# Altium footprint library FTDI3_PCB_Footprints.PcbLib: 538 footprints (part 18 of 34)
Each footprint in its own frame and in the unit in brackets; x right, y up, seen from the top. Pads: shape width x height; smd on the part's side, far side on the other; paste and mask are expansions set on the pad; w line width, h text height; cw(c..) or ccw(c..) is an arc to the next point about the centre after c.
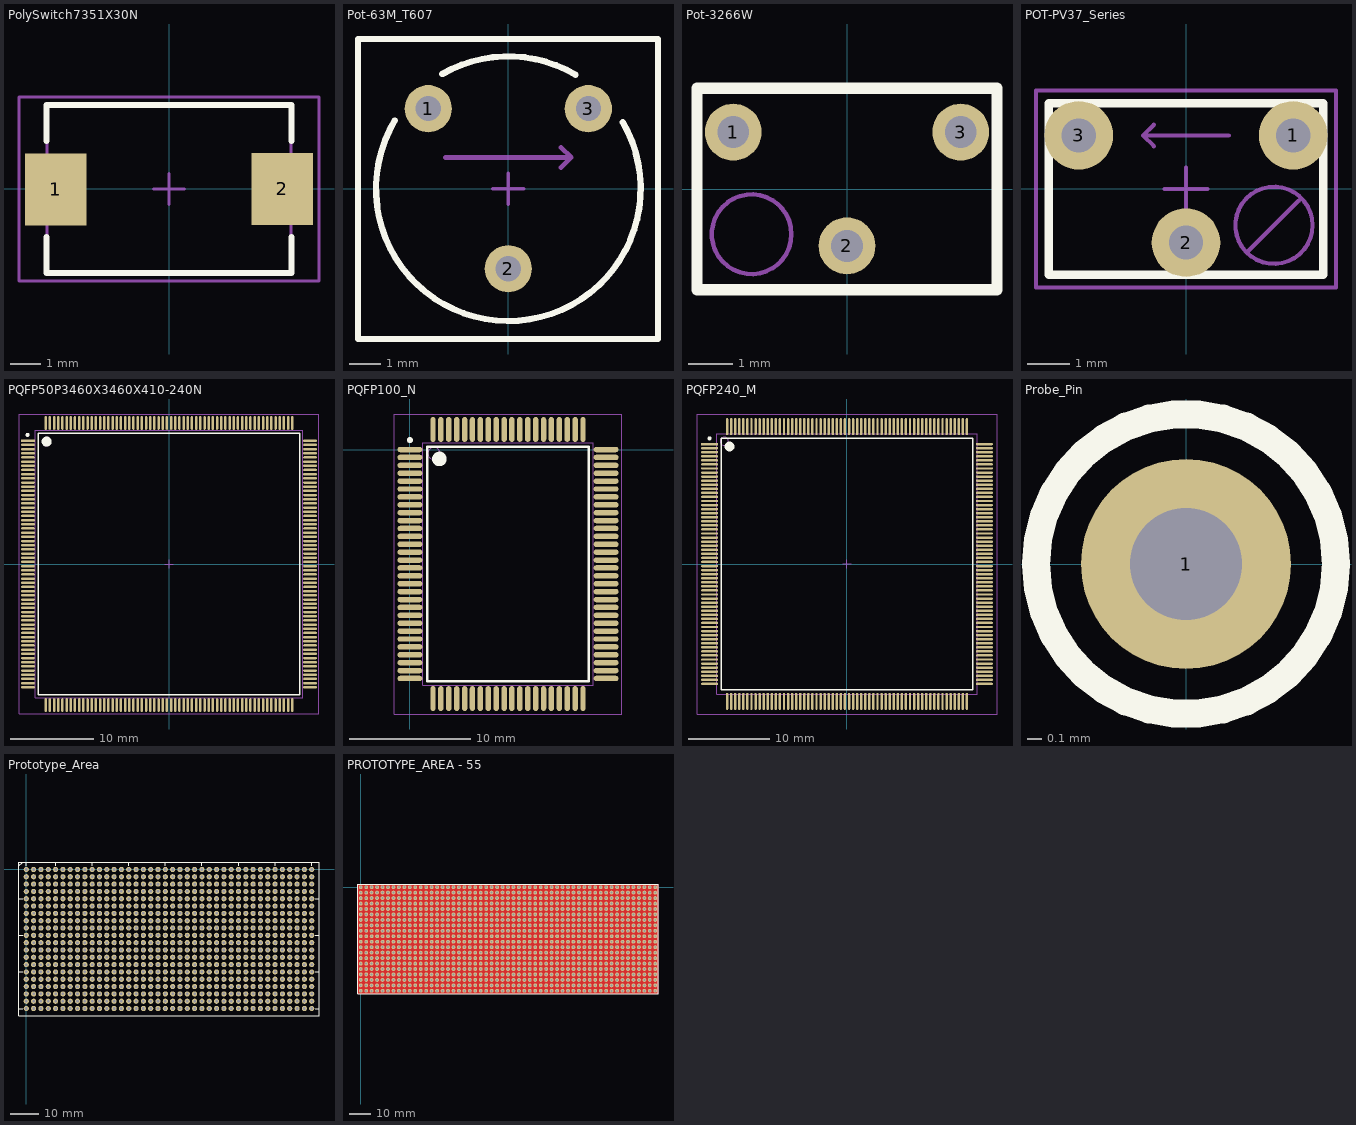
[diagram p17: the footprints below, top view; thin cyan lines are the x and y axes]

## PolySwitch7351X30N [mm] "PolySwitch; SMD300F, 2-Leads, Body 7.3x5.1mm, IPC Medium Density"
height 3
pads (2):
  rect 2x2.35 smd: 1(-3.7,-0.01) 2(3.7,0)
Top Overlay:
  lines w0.2: -4,-1.575 -4,-2.75 4,-2.75 4,-1.575 ; -4,1.575 -4,2.75 4,2.75 4,1.575
M13_Assembly_Info:
  lines w0.1: -3.99,-2.72 -3.99,2.72 3.99,2.72 3.99,-2.72 -3.99,-2.72
M15_Country_Yard:
  lines w0.1: -0.5,0 0.5,0 ; 0,-0.5 0,0.5 ; -4.9,-3 -4.9,3 4.9,3 4.9,-3 -4.9,-3
3D body: height 3, standoff 0, extent -3.99,-2.72 3.99,2.72

## Pot-63M_T607 [mm] "Finger adjustable cermet trimmer"
pads (3):
  round 1.5 hole 0.8: 1(-2.54,2.54) 2(0,-2.54) 3(2.54,2.54)
Top Overlay:
  lines w0.2: -3.601,2.161 ccw(c0,0) 3.634,2.105 ; -2.1,3.638 cw(c0,0) 2.131,3.619 ; -4.77,-4.77 -4.77,4.75 4.75,4.75 4.75,-4.77 -4.77,-4.77
M13_Assembly_Info:
  lines w0.15: -2,0.99 1.99,0.99 ; 1.67,0.67 1.99,0.99 ; 1.67,1.31 1.99,0.99
  text "CW" at -0.71,1.32 h0.8
M15_Country_Yard:
  lines w0.1: -0.5,0 0.5,0 ; 0,-0.5 0,0.5

## Pot-3266W [mil] "Potentiometer"
pads (3):
  round 50 hole 28: 1(-100,50) 2(0,-50) 3(100,50)
Top Overlay:
  lines w10: -131.89,-88.58 -131.89,88.58 131.89,88.58 131.89,-88.58 -131.89,-88.58
M13_Assembly_Info:
  circle w3.94: c-83.86,-39.76 r35.04
  lines w3.94: -131.89,-88.58 -131.89,88.58 131.89,88.58 131.89,-88.58 -131.89,-88.58
3D body: height 0, standoff 0, extent -131.89,-88.58 131.89,88.58

## POT-PV37_Series [mm] "Potentiometer; Multiturn-12; PV37 series; Murata"
pads (3):
  round 1.6 hole 0.8: 1(2.5,1.25) 2(0,-1.25) 3(-2.5,1.25)
Top Overlay:
  lines w0.2: -3.2,-2 -3.2,2 3.2,2 3.2,-2 -3.2,-2
M13_Assembly_Info:
  circle w0.1: c2.053,-0.847 r0.9
  lines w0.1: -0.75,1 -1,1.25 ; -0.75,1.5 -1,1.25 ; 1,1.25 -1,1.25 ; 1.453,-1.447 2.628,-0.272 ; -3.2,-2 -3.2,2 3.2,2 3.2,-2 -3.2,-2
M15_Country_Yard:
  lines w0.1: -0.5,0 0.5,0 ; 0,-0.5 0,0.5 ; -3.5,-2.3 -3.5,2.3 3.5,2.3 3.5,-2.3 -3.5,-2.3

## PQFP50P3460X3460X410-240N [mm] "PQFP, 240-Leads, Body 34.6x34.6mm (max), Pitch 0.50mm, IPC Medium Density"
height 4.1
pads (240):
  rect 1.65x0.3 smd: 1(-16.875,14.75)
  oval 1.65x0.3 smd: 2(-16.875,14.25) 3(-16.875,13.75) 4(-16.875,13.25) 5(-16.875,12.75) 6(-16.875,12.25) 7(-16.875,11.75) 8(-16.875,11.25) 9(-16.875,10.75) 10(-16.875,10.25) 11(-16.875,9.75) 12(-16.875,9.25) 13(-16.875,8.75) 14(-16.875,8.25) 15(-16.875,7.75) 16(-16.875,7.25) 17(-16.875,6.75) 18(-16.875,6.25) 19(-16.875,5.75) 20(-16.875,5.25) 21(-16.875,4.75) 22(-16.875,4.25) 23(-16.875,3.75) 24(-16.875,3.25) 25(-16.875,2.75) 26(-16.875,2.25) 27(-16.875,1.75) 28(-16.875,1.25) 29(-16.875,0.75) 30(-16.875,0.25) 31(-16.875,-0.25) 32(-16.875,-0.75) 33(-16.875,-1.25) 34(-16.875,-1.75) 35(-16.875,-2.25) 36(-16.875,-2.75) 37(-16.875,-3.25) 38(-16.875,-3.75) 39(-16.875,-4.25) 40(-16.875,-4.75) 41(-16.875,-5.25) 42(-16.875,-5.75) 43(-16.875,-6.25) 44(-16.875,-6.75) 45(-16.875,-7.25) 46(-16.875,-7.75) 47(-16.875,-8.25) 48(-16.875,-8.75) 49(-16.875,-9.25) 50(-16.875,-9.75) 51(-16.875,-10.25) 52(-16.875,-10.75) 53(-16.875,-11.25) 54(-16.875,-11.75) 55(-16.875,-12.25) 56(-16.875,-12.75) 57(-16.875,-13.25) 58(-16.875,-13.75) 59(-16.875,-14.25) 60(-16.875,-14.75) 121(16.875,-14.75) 122(16.875,-14.25) 123(16.875,-13.75) 124(16.875,-13.25) 125(16.875,-12.75) 126(16.875,-12.25) 127(16.875,-11.75) 128(16.875,-11.25) 129(16.875,-10.75) 130(16.875,-10.25) 131(16.875,-9.75) 132(16.875,-9.25) 133(16.875,-8.75) 134(16.875,-8.25) 135(16.875,-7.75) 136(16.875,-7.25) 137(16.875,-6.75) 138(16.875,-6.25) 139(16.875,-5.75) 140(16.875,-5.25) 141(16.875,-4.75) 142(16.875,-4.25) 143(16.875,-3.75) 144(16.875,-3.25) 145(16.875,-2.75) 146(16.875,-2.25) 147(16.875,-1.75) 148(16.875,-1.25) 149(16.875,-0.75) 150(16.875,-0.25) 151(16.875,0.25) 152(16.875,0.75) 153(16.875,1.25) 154(16.875,1.75) 155(16.875,2.25) 156(16.875,2.75) 157(16.875,3.25) 158(16.875,3.75) 159(16.875,4.25) 160(16.875,4.75) 161(16.875,5.25) 162(16.875,5.75) 163(16.875,6.25) 164(16.875,6.75) 165(16.875,7.25) 166(16.875,7.75) 167(16.875,8.25) 168(16.875,8.75) 169(16.875,9.25) 170(16.875,9.75) 171(16.875,10.25) 172(16.875,10.75) 173(16.875,11.25) 174(16.875,11.75) 175(16.875,12.25) 176(16.875,12.75) 177(16.875,13.25) 178(16.875,13.75) 179(16.875,14.25) 180(16.875,14.75)
  oval 0.3x1.65 smd: 61(-14.75,-16.875) 62(-14.25,-16.875) 63(-13.75,-16.875) 64(-13.25,-16.875) 65(-12.75,-16.875) 66(-12.25,-16.875) 67(-11.75,-16.875) 68(-11.25,-16.875) 69(-10.75,-16.875) 70(-10.25,-16.875) 71(-9.75,-16.875) 72(-9.25,-16.875) 73(-8.75,-16.875) 74(-8.25,-16.875) 75(-7.75,-16.875) 76(-7.25,-16.875) 77(-6.75,-16.875) 78(-6.25,-16.875) 79(-5.75,-16.875) 80(-5.25,-16.875) 81(-4.75,-16.875) 82(-4.25,-16.875) 83(-3.75,-16.875) 84(-3.25,-16.875) 85(-2.75,-16.875) 86(-2.25,-16.875) 87(-1.75,-16.875) 88(-1.25,-16.875) 89(-0.75,-16.875) 90(-0.25,-16.875) 91(0.25,-16.875) 92(0.75,-16.875) 93(1.25,-16.875) 94(1.75,-16.875) 95(2.25,-16.875) 96(2.75,-16.875) 97(3.25,-16.875) 98(3.75,-16.875) 99(4.25,-16.875) 100(4.75,-16.875) 101(5.25,-16.875) 102(5.75,-16.875) 103(6.25,-16.875) 104(6.75,-16.875) 105(7.25,-16.875) 106(7.75,-16.875) 107(8.25,-16.875) 108(8.75,-16.875) 109(9.25,-16.875) 110(9.75,-16.875) 111(10.25,-16.875) 112(10.75,-16.875) 113(11.25,-16.875) 114(11.75,-16.875) 115(12.25,-16.875) 116(12.75,-16.875) 117(13.25,-16.875) 118(13.75,-16.875) 119(14.25,-16.875) 120(14.75,-16.875) 181(14.75,16.875) 182(14.25,16.875) 183(13.75,16.875) 184(13.25,16.875) 185(12.75,16.875) 186(12.25,16.875) 187(11.75,16.875) 188(11.25,16.875) 189(10.75,16.875) 190(10.25,16.875) 191(9.75,16.875) 192(9.25,16.875) 193(8.75,16.875) 194(8.25,16.875) 195(7.75,16.875) 196(7.25,16.875) 197(6.75,16.875) 198(6.25,16.875) 199(5.75,16.875) 200(5.25,16.875) 201(4.75,16.875) 202(4.25,16.875) 203(3.75,16.875) 204(3.25,16.875) 205(2.75,16.875) 206(2.25,16.875) 207(1.75,16.875) 208(1.25,16.875) 209(0.75,16.875) 210(0.25,16.875) 211(-0.25,16.875) 212(-0.75,16.875) 213(-1.25,16.875) 214(-1.75,16.875) 215(-2.25,16.875) 216(-2.75,16.875) 217(-3.25,16.875) 218(-3.75,16.875) 219(-4.25,16.875) 220(-4.75,16.875) 221(-5.25,16.875) 222(-5.75,16.875) 223(-6.25,16.875) 224(-6.75,16.875) 225(-7.25,16.875) 226(-7.75,16.875) 227(-8.25,16.875) 228(-8.75,16.875) 229(-9.25,16.875) 230(-9.75,16.875) 231(-10.25,16.875) 232(-10.75,16.875) 233(-11.25,16.875) 234(-11.75,16.875) 235(-12.25,16.875) 236(-12.75,16.875) 237(-13.25,16.875) 238(-13.75,16.875) 239(-14.25,16.875) 240(-14.75,16.875)
Top Overlay:
  circle w0.6: c-14.65,14.65 r0.3
  circle w0.25: c-16.925,15.45 r0.125
  lines w0.2: -15.65,-15.65 15.65,-15.65 15.65,15.65 -15.65,15.65 -15.65,-15.65
M13_Assembly_Info:
  circle w0.1: c-14.65,14.65 r0.5
  lines w0.1: -16,-16 16,-16 16,16 -16,16 -16,-16
M15_Country_Yard:
  lines w0.1: -0.5,0 0.5,0 ; 0,-0.5 0,0.5 ; -17.95,-17.95 17.95,-17.95 17.95,17.95 -17.95,17.95 -17.95,-17.95
3D body: height 4.1, standoff 0.5, extent -16,-16 16,16

## PQFP100_N [mm] "QFP, 100-Leads, Body 20x14mm, Pitch 0.65mm, IPC Medium Density"
height 3.4
pads (100):
  oval 2.05x0.45 smd: 1(0,0) 2(0,-0.65) 3(0,-1.3) 4(0,-1.95) 5(0,-2.6) 6(0,-3.25) 7(0,-3.9) 8(0,-4.55) 9(0,-5.2) 10(0,-5.85) 11(0,-6.5) 12(0,-7.15) 13(0,-7.8) 14(0,-8.45) 15(0,-9.1) 16(0,-9.75) 17(0,-10.4) 18(0,-11.05) 19(0,-11.7) 20(0,-12.35) 21(0,-13) 22(0,-13.65) 23(0,-14.3) 24(0,-14.95) 25(0,-15.6) 26(0,-16.25) 27(0,-16.9) 28(0,-17.55) 29(0,-18.2) 30(0,-18.85) 51(16.15,-18.85) 52(16.15,-18.2) 53(16.15,-17.55) 54(16.15,-16.9) 55(16.15,-16.25) 56(16.15,-15.6) 57(16.15,-14.95) 58(16.15,-14.3) 59(16.15,-13.65) 60(16.15,-13) 61(16.15,-12.35) 62(16.15,-11.7) 63(16.15,-11.05) 64(16.15,-10.4) 65(16.15,-9.75) 66(16.15,-9.1) 67(16.15,-8.45) 68(16.15,-7.8) 69(16.15,-7.15) 70(16.15,-6.5) 71(16.15,-5.85) 72(16.15,-5.2) 73(16.15,-4.55) 74(16.15,-3.9) 75(16.15,-3.25) 76(16.15,-2.6) 77(16.15,-1.95) 78(16.15,-1.3) 79(16.15,-0.65) 80(16.15,0)
  oval 0.45x2.05 smd: 31(1.9,-20.5) 32(2.55,-20.5) 33(3.2,-20.5) 34(3.85,-20.5) 35(4.5,-20.5) 36(5.15,-20.5) 37(5.8,-20.5) 38(6.45,-20.5) 39(7.1,-20.5) 40(7.75,-20.5) 41(8.4,-20.5) 42(9.05,-20.5) 43(9.7,-20.5) 44(10.35,-20.5) 45(11,-20.5) 46(11.65,-20.5) 47(12.3,-20.5) 48(12.95,-20.5) 49(13.6,-20.5) 50(14.25,-20.5) 81(14.25,1.65) 82(13.6,1.65) 83(12.95,1.65) 84(12.3,1.65) 85(11.65,1.65) 86(11,1.65) 87(10.35,1.65) 88(9.7,1.65) 89(9.05,1.65) 90(8.4,1.65) 91(7.75,1.65) 92(7.1,1.65) 93(6.45,1.65) 94(5.8,1.65) 95(5.15,1.65) 96(4.5,1.65) 97(3.85,1.65) 98(3.2,1.65) 99(2.55,1.65) 100(1.9,1.65)
Top Overlay:
  circle w0.25: c0,0.775 r0.125
  circle w0.6: c2.425,-0.775 r0.3
  lines w0.2: 1.425,-19.075 1.425,0.225 14.725,0.225 14.725,-19.075 1.425,-19.075
M13_Assembly_Info:
  circle w0.1: c1.975,-0.325 r0.5
  lines w0.1: 1.075,-19.425 1.075,0.575 15.075,0.575 15.075,-19.425 1.075,-19.425
M15_Country_Yard:
  lines w0.1: -1.275,-21.775 -1.275,2.925 17.425,2.925 17.425,-21.775 -1.275,-21.775
3D body: height 3.4, standoff 0, extent 1.075,-19.425 15.075,0.575

## PQFP240_M [mm] "Shrink QFP, 240-Leads, Body 32x32mm, Pitch 0.5mm, IPC Low Density"
height 4.1
pads (240):
  rect 2.1x0.3 smd: 1(-16.9,14.75)
  oval 2.1x0.3 smd: 2(-16.9,14.25) 3(-16.9,13.75) 4(-16.9,13.25) 5(-16.9,12.75) 6(-16.9,12.25) 7(-16.9,11.75) 8(-16.9,11.25) 9(-16.9,10.75) 10(-16.9,10.25) 11(-16.9,9.75) 12(-16.9,9.25) 13(-16.9,8.75) 14(-16.9,8.25) 15(-16.9,7.75) 16(-16.9,7.25) 17(-16.9,6.75) 18(-16.9,6.25) 19(-16.9,5.75) 20(-16.9,5.25) 21(-16.9,4.75) 22(-16.9,4.25) 23(-16.9,3.75) 24(-16.9,3.25) 25(-16.9,2.75) 26(-16.9,2.25) 27(-16.9,1.75) 28(-16.9,1.25) 29(-16.9,0.75) 30(-16.9,0.25) 31(-16.9,-0.25) 32(-16.9,-0.75) 33(-16.9,-1.25) 34(-16.9,-1.75) 35(-16.9,-2.25) 36(-16.9,-2.75) 37(-16.9,-3.25) 38(-16.9,-3.75) 39(-16.9,-4.25) 40(-16.9,-4.75) 41(-16.9,-5.25) 42(-16.9,-5.75) 43(-16.9,-6.25) 44(-16.9,-6.75) 45(-16.9,-7.25) 46(-16.9,-7.75) 47(-16.9,-8.25) 48(-16.9,-8.75) 49(-16.9,-9.25) 50(-16.9,-9.75) 51(-16.9,-10.25) 52(-16.9,-10.75) 53(-16.9,-11.25) 54(-16.9,-11.75) 55(-16.9,-12.25) 56(-16.9,-12.75) 57(-16.9,-13.25) 58(-16.9,-13.75) 59(-16.9,-14.25) 60(-16.9,-14.75) 121(16.9,-14.75) 122(16.9,-14.25) 123(16.9,-13.75) 124(16.9,-13.25) 125(16.9,-12.75) 126(16.9,-12.25) 127(16.9,-11.75) 128(16.9,-11.25) 129(16.9,-10.75) 130(16.9,-10.25) 131(16.9,-9.75) 132(16.9,-9.25) 133(16.9,-8.75) 134(16.9,-8.25) 135(16.9,-7.75) 136(16.9,-7.25) 137(16.9,-6.75) 138(16.9,-6.25) 139(16.9,-5.75) 140(16.9,-5.25) 141(16.9,-4.75) 142(16.9,-4.25) 143(16.9,-3.75) 144(16.9,-3.25) 145(16.9,-2.75) 146(16.9,-2.25) 147(16.9,-1.75) 148(16.9,-1.25) 149(16.9,-0.75) 150(16.9,-0.25) 151(16.9,0.25) 152(16.9,0.75) 153(16.9,1.25) 154(16.9,1.75) 155(16.9,2.25) 156(16.9,2.75) 157(16.9,3.25) 158(16.9,3.75) 159(16.9,4.25) 160(16.9,4.75) 161(16.9,5.25) 162(16.9,5.75) 163(16.9,6.25) 164(16.9,6.75) 165(16.9,7.25) 166(16.9,7.75) 167(16.9,8.25) 168(16.9,8.75) 169(16.9,9.25) 170(16.9,9.75) 171(16.9,10.25) 172(16.9,10.75) 173(16.9,11.25) 174(16.9,11.75) 175(16.9,12.25) 176(16.9,12.75) 177(16.9,13.25) 178(16.9,13.75) 179(16.9,14.25) 180(16.9,14.75)
  oval 0.3x2.1 smd: 61(-14.75,-16.9) 62(-14.25,-16.9) 63(-13.75,-16.9) 64(-13.25,-16.9) 65(-12.75,-16.9) 66(-12.25,-16.9) 67(-11.75,-16.9) 68(-11.25,-16.9) 69(-10.75,-16.9) 70(-10.25,-16.9) 71(-9.75,-16.9) 72(-9.25,-16.9) 73(-8.75,-16.9) 74(-8.25,-16.9) 75(-7.75,-16.9) 76(-7.25,-16.9) 77(-6.75,-16.9) 78(-6.25,-16.9) 79(-5.75,-16.9) 80(-5.25,-16.9) 81(-4.75,-16.9) 82(-4.25,-16.9) 83(-3.75,-16.9) 84(-3.25,-16.9) 85(-2.75,-16.9) 86(-2.25,-16.9) 87(-1.75,-16.9) 88(-1.25,-16.9) 89(-0.75,-16.9) 90(-0.25,-16.9) 91(0.25,-16.9) 92(0.75,-16.9) 93(1.25,-16.9) 94(1.75,-16.9) 95(2.25,-16.9) 96(2.75,-16.9) 97(3.25,-16.9) 98(3.75,-16.9) 99(4.25,-16.9) 100(4.75,-16.9) 101(5.25,-16.9) 102(5.75,-16.9) 103(6.25,-16.9) 104(6.75,-16.9) 105(7.25,-16.9) 106(7.75,-16.9) 107(8.25,-16.9) 108(8.75,-16.9) 109(9.25,-16.9) 110(9.75,-16.9) 111(10.25,-16.9) 112(10.75,-16.9) 113(11.25,-16.9) 114(11.75,-16.9) 115(12.25,-16.9) 116(12.75,-16.9) 117(13.25,-16.9) 118(13.75,-16.9) 119(14.25,-16.9) 120(14.75,-16.9) 181(14.75,16.9) 182(14.25,16.9) 183(13.75,16.9) 184(13.25,16.9) 185(12.75,16.9) 186(12.25,16.9) 187(11.75,16.9) 188(11.25,16.9) 189(10.75,16.9) 190(10.25,16.9) 191(9.75,16.9) 192(9.25,16.9) 193(8.75,16.9) 194(8.25,16.9) 195(7.75,16.9) 196(7.25,16.9) 197(6.75,16.9) 198(6.25,16.9) 199(5.75,16.9) 200(5.25,16.9) 201(4.75,16.9) 202(4.25,16.9) 203(3.75,16.9) 204(3.25,16.9) 205(2.75,16.9) 206(2.25,16.9) 207(1.75,16.9) 208(1.25,16.9) 209(0.75,16.9) 210(0.25,16.9) 211(-0.25,16.9) 212(-0.75,16.9) 213(-1.25,16.9) 214(-1.75,16.9) 215(-2.25,16.9) 216(-2.75,16.9) 217(-3.25,16.9) 218(-3.75,16.9) 219(-4.25,16.9) 220(-4.75,16.9) 221(-5.25,16.9) 222(-5.75,16.9) 223(-6.25,16.9) 224(-6.75,16.9) 225(-7.25,16.9) 226(-7.75,16.9) 227(-8.25,16.9) 228(-8.75,16.9) 229(-9.25,16.9) 230(-9.75,16.9) 231(-10.25,16.9) 232(-10.75,16.9) 233(-11.25,16.9) 234(-11.75,16.9) 235(-12.25,16.9) 236(-12.75,16.9) 237(-13.25,16.9) 238(-13.75,16.9) 239(-14.25,16.9) 240(-14.75,16.9)
Top Overlay:
  circle w0.6: c-14.45,14.45 r0.3
  circle w0.25: c-16.9,15.45 r0.125
  lines w0.2: -15.45,-15.45 15.45,-15.45 15.45,15.45 -15.45,15.45 -15.45,-15.45
M13_Assembly_Info:
  circle w0.1: c-15.1,15.1 r0.5
  lines w0.1: -16,-16 16,-16 16,16 -16,16 -16,-16
M15_Country_Yard:
  lines w0.1: -0.5,0 0.5,0 ; 0,-0.5 0,0.5 ; -18.45,-18.45 18.45,-18.45 18.45,18.45 -18.45,18.45 -18.45,-18.45
3D body: height 4.1, standoff 0, extent -16,-16 16,16

## Probe_Pin [mm] "Probe Pin"
height 4.6
pads (1):
  round 1.5 hole 0.8: 1(0,0)
Top Overlay:
  circle w0.2: c0,0 r1.07
3D body: height 3, standoff 0, extent -1.245,-1.25 1.25,1.24

## Prototype_Area [mm] "Prototype area; 40 cols x 20 rows"
pads (800):
  round 1.8 hole 0.9: 1(0,0) 2(2.54,0) 3(5.08,0) 4(7.62,0) 5(10.16,0) 6(12.7,0) 7(15.24,0) 8(17.78,0) 9(20.32,0) 10(22.86,0) 11(25.4,0) 12(27.94,0) 13(30.48,0) 14(33.02,0) 15(35.56,0) 16(38.1,0) 17(40.64,0) 18(43.18,0) 19(45.72,0) 20(48.26,0) 21(50.8,0) 22(53.34,0) 23(55.88,0) 24(58.42,0) 25(60.96,0) 26(63.5,0) 27(66.04,0) 28(68.58,0) 29(71.12,0) 30(73.66,0) 31(76.2,0) 32(78.74,0) 33(81.28,0) 34(83.82,0) 35(86.36,0) 36(88.9,0) 37(91.44,0) 38(93.98,0) 39(96.52,0) 40(99.06,0) ""(0,-48.26) ""(0,-45.72) ""(0,-43.18) ""(0,-40.64) ""(0,-38.1) ""(0,-35.56) ""(0,-33.02) ""(0,-30.48) ""(0,-27.94) ""(0,-25.4) ""(0,-22.86) ""(0,-20.32) ""(0,-17.78) ""(0,-15.24) ""(0,-12.7) ""(0,-10.16) ""(0,-7.62) ""(0,-5.08) ""(0,-2.54) ""(2.54,-48.26) ""(2.54,-45.72) ""(2.54,-43.18) ""(2.54,-40.64) ""(2.54,-38.1) ""(2.54,-35.56) ""(2.54,-33.02) ""(2.54,-30.48) ""(2.54,-27.94) ""(2.54,-25.4) ""(2.54,-22.86) ""(2.54,-20.32) ""(2.54,-17.78) ""(2.54,-15.24) ""(2.54,-12.7) ""(2.54,-10.16) ""(2.54,-7.62) ""(2.54,-5.08) ""(2.54,-2.54) ""(5.08,-48.26) ""(5.08,-45.72) ""(5.08,-43.18) ""(5.08,-40.64) ""(5.08,-38.1) ""(5.08,-35.56) ""(5.08,-33.02) ""(5.08,-30.48) ""(5.08,-27.94) ""(5.08,-25.4) ""(5.08,-22.86) ""(5.08,-20.32) ""(5.08,-17.78) ""(5.08,-15.24) ""(5.08,-12.7) ""(5.08,-10.16) ""(5.08,-7.62) ""(5.08,-5.08) ""(5.08,-2.54) ""(7.62,-48.26) ""(7.62,-45.72) ""(7.62,-43.18) ""(7.62,-40.64) ""(7.62,-38.1) ""(7.62,-35.56) ""(7.62,-33.02) ""(7.62,-30.48) ""(7.62,-27.94) ""(7.62,-25.4) ""(7.62,-22.86) ""(7.62,-20.32) ""(7.62,-17.78) ""(7.62,-15.24) ""(7.62,-12.7) ""(7.62,-10.16) ""(7.62,-7.62) ""(7.62,-5.08) ""(7.62,-2.54) ""(10.16,-48.26) ""(10.16,-45.72) ""(10.16,-43.18) ""(10.16,-40.64) ""(10.16,-38.1) ""(10.16,-35.56) ""(10.16,-33.02) ""(10.16,-30.48) ""(10.16,-27.94) ""(10.16,-25.4) ""(10.16,-22.86) ""(10.16,-20.32) ""(10.16,-17.78) ""(10.16,-15.24) ""(10.16,-12.7) ""(10.16,-10.16) ""(10.16,-7.62) ""(10.16,-5.08) ""(10.16,-2.54) ""(12.7,-48.26) ""(12.7,-45.72) ""(12.7,-43.18) ""(12.7,-40.64) ""(12.7,-38.1) ""(12.7,-35.56) ""(12.7,-33.02) ""(12.7,-30.48) ""(12.7,-27.94) ""(12.7,-25.4) ""(12.7,-22.86) ""(12.7,-20.32) ""(12.7,-17.78) ""(12.7,-15.24) ""(12.7,-12.7) ""(12.7,-10.16) ""(12.7,-7.62) ""(12.7,-5.08) ""(12.7,-2.54) ""(15.24,-48.26) ""(15.24,-45.72) ""(15.24,-43.18) ""(15.24,-40.64) ""(15.24,-38.1) ""(15.24,-35.56) ""(15.24,-33.02) ""(15.24,-30.48) ""(15.24,-27.94) ""(15.24,-25.4) ""(15.24,-22.86) ""(15.24,-20.32) ""(15.24,-17.78) ""(15.24,-15.24) ""(15.24,-12.7) ""(15.24,-10.16) ""(15.24,-7.62) ""(15.24,-5.08) ""(15.24,-2.54) ""(17.78,-48.26) ""(17.78,-45.72) ""(17.78,-43.18) ""(17.78,-40.64) ""(17.78,-38.1) ""(17.78,-35.56) ""(17.78,-33.02) ""(17.78,-30.48) ""(17.78,-27.94) ""(17.78,-25.4) ""(17.78,-22.86) ""(17.78,-20.32) ""(17.78,-17.78) ""(17.78,-15.24) ""(17.78,-12.7) ""(17.78,-10.16) ""(17.78,-7.62) ""(17.78,-5.08) ""(17.78,-2.54) ""(20.32,-48.26) ""(20.32,-45.72) ""(20.32,-43.18) ""(20.32,-40.64) ""(20.32,-38.1) ""(20.32,-35.56) ""(20.32,-33.02) ""(20.32,-30.48) ""(20.32,-27.94) ""(20.32,-25.4) ""(20.32,-22.86) ""(20.32,-20.32) ""(20.32,-17.78) ""(20.32,-15.24) ""(20.32,-12.7) ""(20.32,-10.16) ""(20.32,-7.62) ""(20.32,-5.08) ""(20.32,-2.54) ""(22.86,-48.26) ""(22.86,-45.72) ""(22.86,-43.18) ""(22.86,-40.64) ""(22.86,-38.1) ""(22.86,-35.56) ""(22.86,-33.02) ""(22.86,-30.48) ""(22.86,-27.94) ""(22.86,-25.4) ""(22.86,-22.86) ""(22.86,-20.32) ""(22.86,-17.78) ""(22.86,-15.24) ""(22.86,-12.7) ""(22.86,-10.16) ""(22.86,-7.62) ""(22.86,-5.08) ""(22.86,-2.54) ""(25.4,-48.26) ""(25.4,-45.72) ""(25.4,-43.18) ""(25.4,-40.64) ""(25.4,-38.1) ""(25.4,-35.56) ""(25.4,-33.02) ""(25.4,-30.48) ""(25.4,-27.94) ""(25.4,-25.4) ""(25.4,-22.86) ""(25.4,-20.32) ""(25.4,-17.78) ""(25.4,-15.24) ""(25.4,-12.7) ""(25.4,-10.16) ""(25.4,-7.62) ""(25.4,-5.08) ""(25.4,-2.54) ""(27.94,-48.26) ""(27.94,-45.72) ""(27.94,-43.18) ""(27.94,-40.64) ""(27.94,-38.1) ""(27.94,-35.56) ""(27.94,-33.02) ""(27.94,-30.48) ""(27.94,-27.94) ""(27.94,-25.4) ""(27.94,-22.86) ""(27.94,-20.32) ""(27.94,-17.78) ""(27.94,-15.24) ""(27.94,-12.7) ""(27.94,-10.16) ""(27.94,-7.62) ""(27.94,-5.08) ""(27.94,-2.54) ""(30.48,-48.26) ""(30.48,-45.72) ""(30.48,-43.18) ""(30.48,-40.64) ""(30.48,-38.1) ""(30.48,-35.56) ""(30.48,-33.02) ""(30.48,-30.48) ""(30.48,-27.94) ""(30.48,-25.4) ""(30.48,-22.86) ""(30.48,-20.32) ""(30.48,-17.78) ""(30.48,-15.24) ""(30.48,-12.7) ""(30.48,-10.16) ""(30.48,-7.62) ""(30.48,-5.08) ""(30.48,-2.54) ""(33.02,-48.26) ""(33.02,-45.72) ""(33.02,-43.18) ""(33.02,-40.64) ""(33.02,-38.1) ""(33.02,-35.56) ""(33.02,-33.02) ""(33.02,-30.48) ""(33.02,-27.94) ""(33.02,-25.4) ""(33.02,-22.86) ""(33.02,-20.32) ""(33.02,-17.78) ""(33.02,-15.24) ""(33.02,-12.7) ""(33.02,-10.16) ""(33.02,-7.62) ""(33.02,-5.08) ""(33.02,-2.54) ""(35.56,-48.26) ""(35.56,-45.72) ""(35.56,-43.18) ""(35.56,-40.64) ""(35.56,-38.1) ""(35.56,-35.56) ""(35.56,-33.02) ""(35.56,-30.48) ""(35.56,-27.94) ""(35.56,-25.4) ""(35.56,-22.86) ""(35.56,-20.32) ""(35.56,-17.78) ""(35.56,-15.24) ""(35.56,-12.7) ""(35.56,-10.16) ""(35.56,-7.62) ""(35.56,-5.08) ""(35.56,-2.54) ""(38.1,-48.26) ""(38.1,-45.72) ""(38.1,-43.18) ""(38.1,-40.64) ""(38.1,-38.1) ""(38.1,-35.56) ""(38.1,-33.02) ""(38.1,-30.48) ""(38.1,-27.94) ""(38.1,-25.4) ""(38.1,-22.86) ""(38.1,-20.32) ""(38.1,-17.78) ""(38.1,-15.24) ""(38.1,-12.7) ""(38.1,-10.16) ""(38.1,-7.62) ""(38.1,-5.08) ""(38.1,-2.54) ""(40.64,-48.26) ""(40.64,-45.72) ""(40.64,-43.18) ""(40.64,-40.64) ""(40.64,-38.1) ""(40.64,-35.56) ""(40.64,-33.02) ""(40.64,-30.48) ""(40.64,-27.94) ""(40.64,-25.4) ""(40.64,-22.86) ""(40.64,-20.32) ""(40.64,-17.78) ""(40.64,-15.24) ""(40.64,-12.7) ""(40.64,-10.16) ""(40.64,-7.62) ""(40.64,-5.08) ""(40.64,-2.54) ""(43.18,-48.26) ""(43.18,-45.72) ""(43.18,-43.18) ""(43.18,-40.64) ""(43.18,-38.1) ""(43.18,-35.56) ""(43.18,-33.02) ""(43.18,-30.48) ""(43.18,-27.94) ""(43.18,-25.4) ""(43.18,-22.86) ""(43.18,-20.32) ""(43.18,-17.78) ""(43.18,-15.24) ""(43.18,-12.7) ""(43.18,-10.16) ""(43.18,-7.62) ""(43.18,-5.08) ""(43.18,-2.54) ""(45.72,-48.26) ""(45.72,-45.72) ""(45.72,-43.18) ""(45.72,-40.64) ""(45.72,-38.1) ""(45.72,-35.56) ""(45.72,-33.02) ""(45.72,-30.48) ""(45.72,-27.94) ""(45.72,-25.4) ""(45.72,-22.86) ""(45.72,-20.32) ""(45.72,-17.78) ""(45.72,-15.24) ""(45.72,-12.7) ""(45.72,-10.16) ""(45.72,-7.62) ""(45.72,-5.08) ""(45.72,-2.54) ""(48.26,-48.26) ""(48.26,-45.72) ""(48.26,-43.18) ""(48.26,-40.64) ""(48.26,-38.1) ""(48.26,-35.56) ""(48.26,-33.02) ""(48.26,-30.48) ""(48.26,-27.94) ""(48.26,-25.4) ""(48.26,-22.86) ""(48.26,-20.32) ""(48.26,-17.78) ""(48.26,-15.24) ""(48.26,-12.7) ""(48.26,-10.16) ""(48.26,-7.62) ""(48.26,-5.08) ""(48.26,-2.54) ""(50.8,-48.26) ""(50.8,-45.72) ""(50.8,-43.18) ""(50.8,-40.64) ""(50.8,-38.1) ""(50.8,-35.56) ""(50.8,-33.02) ""(50.8,-30.48) ""(50.8,-27.94) ""(50.8,-25.4) ""(50.8,-22.86) ""(50.8,-20.32) ""(50.8,-17.78) ""(50.8,-15.24) ""(50.8,-12.7) ""(50.8,-10.16) ""(50.8,-7.62) ""(50.8,-5.08) ""(50.8,-2.54) ""(53.34,-48.26) ""(53.34,-45.72) ""(53.34,-43.18) ""(53.34,-40.64) ""(53.34,-38.1) ""(53.34,-35.56) ""(53.34,-33.02) ""(53.34,-30.48) ""(53.34,-27.94) ""(53.34,-25.4) ""(53.34,-22.86) ""(53.34,-20.32) ""(53.34,-17.78) ""(53.34,-15.24) ""(53.34,-12.7) ""(53.34,-10.16) ""(53.34,-7.62) ""(53.34,-5.08) ""(53.34,-2.54) ""(55.88,-48.26) ""(55.88,-45.72) ""(55.88,-43.18) ""(55.88,-40.64) ""(55.88,-38.1) ""(55.88,-35.56) ""(55.88,-33.02) ""(55.88,-30.48) ""(55.88,-27.94) ""(55.88,-25.4) ""(55.88,-22.86) ""(55.88,-20.32) ""(55.88,-17.78) ""(55.88,-15.24) ""(55.88,-12.7) ""(55.88,-10.16) ""(55.88,-7.62) ""(55.88,-5.08) ""(55.88,-2.54) ""(58.42,-48.26) ""(58.42,-45.72) ""(58.42,-43.18) ""(58.42,-40.64) ""(58.42,-38.1) ""(58.42,-35.56) ""(58.42,-33.02) ""(58.42,-30.48) ""(58.42,-27.94) ""(58.42,-25.4) ""(58.42,-22.86) ""(58.42,-20.32) ""(58.42,-17.78) ""(58.42,-15.24) ""(58.42,-12.7) ""(58.42,-10.16) ""(58.42,-7.62) ""(58.42,-5.08) ""(58.42,-2.54) ""(60.96,-48.26) ""(60.96,-45.72) ""(60.96,-43.18) ""(60.96,-40.64) ""(60.96,-38.1) ""(60.96,-35.56) ""(60.96,-33.02) ""(60.96,-30.48) ""(60.96,-27.94) ""(60.96,-25.4) ""(60.96,-22.86) ""(60.96,-20.32) ""(60.96,-17.78) ""(60.96,-15.24) ""(60.96,-12.7) ""(60.96,-10.16) ""(60.96,-7.62) ""(60.96,-5.08) ""(60.96,-2.54) ""(63.5,-48.26) ""(63.5,-45.72) ""(63.5,-43.18) ""(63.5,-40.64) ""(63.5,-38.1) ""(63.5,-35.56) ""(63.5,-33.02) ""(63.5,-30.48) ""(63.5,-27.94) ""(63.5,-25.4) ""(63.5,-22.86) ""(63.5,-20.32) ""(63.5,-17.78) ""(63.5,-15.24) ""(63.5,-12.7) ""(63.5,-10.16) ""(63.5,-7.62) ""(63.5,-5.08) ""(63.5,-2.54) ""(66.04,-48.26) ""(66.04,-45.72) ""(66.04,-43.18) ""(66.04,-40.64) ""(66.04,-38.1) ""(66.04,-35.56) ""(66.04,-33.02) ""(66.04,-30.48) ""(66.04,-27.94) ""(66.04,-25.4) ""(66.04,-22.86) ""(66.04,-20.32) ""(66.04,-17.78) ""(66.04,-15.24) ""(66.04,-12.7) ""(66.04,-10.16) ""(66.04,-7.62) ""(66.04,-5.08) ""(66.04,-2.54) ""(68.58,-48.26) ""(68.58,-45.72) ""(68.58,-43.18) ""(68.58,-40.64) ""(68.58,-38.1) ""(68.58,-35.56) ""(68.58,-33.02) ""(68.58,-30.48) ""(68.58,-27.94) ""(68.58,-25.4) ""(68.58,-22.86) ""(68.58,-20.32) ""(68.58,-17.78) ""(68.58,-15.24) ""(68.58,-12.7) ""(68.58,-10.16) ""(68.58,-7.62) ""(68.58,-5.08) ""(68.58,-2.54) ""(71.12,-48.26) ""(71.12,-45.72) ""(71.12,-43.18) ""(71.12,-40.64) ""(71.12,-38.1) ""(71.12,-35.56) ""(71.12,-33.02) ""(71.12,-30.48) ""(71.12,-27.94) ""(71.12,-25.4) ""(71.12,-22.86) ""(71.12,-20.32) ""(71.12,-17.78) ""(71.12,-15.24) ""(71.12,-12.7) ""(71.12,-10.16) ""(71.12,-7.62) ""(71.12,-5.08) ""(71.12,-2.54) ""(73.66,-48.26) ""(73.66,-45.72) ""(73.66,-43.18) ""(73.66,-40.64) ""(73.66,-38.1) ""(73.66,-35.56) ""(73.66,-33.02) ""(73.66,-30.48) ""(73.66,-27.94) ""(73.66,-25.4) ""(73.66,-22.86) ""(73.66,-20.32) ""(73.66,-17.78) ""(73.66,-15.24) ""(73.66,-12.7) ""(73.66,-10.16) ""(73.66,-7.62) ""(73.66,-5.08) ""(73.66,-2.54) ""(76.2,-48.26) ""(76.2,-45.72) ""(76.2,-43.18) ""(76.2,-40.64) ""(76.2,-38.1) ""(76.2,-35.56) ""(76.2,-33.02) ""(76.2,-30.48) ""(76.2,-27.94) ""(76.2,-25.4) ""(76.2,-22.86) ""(76.2,-20.32) ""(76.2,-17.78) ""(76.2,-15.24) ""(76.2,-12.7) ""(76.2,-10.16) ""(76.2,-7.62) ""(76.2,-5.08) ""(76.2,-2.54) ""(78.74,-48.26) ""(78.74,-45.72) ""(78.74,-43.18) ""(78.74,-40.64) ""(78.74,-38.1) ""(78.74,-35.56) ""(78.74,-33.02) ""(78.74,-30.48) ""(78.74,-27.94) ""(78.74,-25.4) ""(78.74,-22.86) ""(78.74,-20.32) ""(78.74,-17.78) ""(78.74,-15.24) ""(78.74,-12.7) ""(78.74,-10.16) ""(78.74,-7.62) ""(78.74,-5.08) ""(78.74,-2.54) ""(81.28,-48.26) ""(81.28,-45.72) ""(81.28,-43.18) ""(81.28,-40.64) ""(81.28,-38.1) ""(81.28,-35.56) ""(81.28,-33.02) ""(81.28,-30.48) ""(81.28,-27.94) ""(81.28,-25.4) ""(81.28,-22.86) ""(81.28,-20.32) ""(81.28,-17.78) ""(81.28,-15.24) ""(81.28,-12.7) ""(81.28,-10.16) ""(81.28,-7.62) ""(81.28,-5.08) ""(81.28,-2.54) ""(83.82,-48.26) ""(83.82,-45.72) ""(83.82,-43.18) ""(83.82,-40.64) ""(83.82,-38.1) ""(83.82,-35.56) ""(83.82,-33.02) ""(83.82,-30.48) ""(83.82,-27.94) ""(83.82,-25.4) ""(83.82,-22.86) ""(83.82,-20.32) ""(83.82,-17.78) ""(83.82,-15.24) ""(83.82,-12.7) ""(83.82,-10.16) ""(83.82,-7.62) ""(83.82,-5.08) ""(83.82,-2.54) ""(86.36,-48.26) ""(86.36,-45.72) ""(86.36,-43.18) ""(86.36,-40.64) ""(86.36,-38.1) ""(86.36,-35.56) ""(86.36,-33.02) ""(86.36,-30.48) ""(86.36,-27.94) ""(86.36,-25.4) ""(86.36,-22.86) ""(86.36,-20.32) ""(86.36,-17.78) ""(86.36,-15.24) ""(86.36,-12.7) ""(86.36,-10.16) ""(86.36,-7.62) ""(86.36,-5.08) ""(86.36,-2.54) ""(88.9,-48.26) ""(88.9,-45.72) ""(88.9,-43.18) ""(88.9,-40.64) ""(88.9,-38.1) ""(88.9,-35.56) ""(88.9,-33.02) ""(88.9,-30.48) ""(88.9,-27.94) ""(88.9,-25.4) ""(88.9,-22.86) ""(88.9,-20.32) ""(88.9,-17.78) ""(88.9,-15.24) ""(88.9,-12.7) ""(88.9,-10.16) ""(88.9,-7.62) ""(88.9,-5.08) ""(88.9,-2.54) ""(91.44,-48.26) ""(91.44,-45.72) ""(91.44,-43.18) ""(91.44,-40.64) ""(91.44,-38.1) ""(91.44,-35.56) ""(91.44,-33.02) ""(91.44,-30.48) ""(91.44,-27.94) ""(91.44,-25.4) ""(91.44,-22.86) ""(91.44,-20.32) ""(91.44,-17.78) ""(91.44,-15.24) ""(91.44,-12.7) ""(91.44,-10.16) ""(91.44,-7.62) ""(91.44,-5.08) ""(91.44,-2.54) ""(93.98,-48.26) ""(93.98,-45.72) ""(93.98,-43.18) ""(93.98,-40.64) ""(93.98,-38.1) ""(93.98,-35.56) ""(93.98,-33.02) ""(93.98,-30.48) ""(93.98,-27.94) ""(93.98,-25.4) ""(93.98,-22.86) ""(93.98,-20.32) ""(93.98,-17.78) ""(93.98,-15.24) ""(93.98,-12.7) ""(93.98,-10.16) ""(93.98,-7.62) ""(93.98,-5.08) ""(93.98,-2.54) ""(96.52,-48.26) ""(96.52,-45.72) ""(96.52,-43.18) ""(96.52,-40.64) ""(96.52,-38.1) ""(96.52,-35.56) ""(96.52,-33.02) ""(96.52,-30.48) ""(96.52,-27.94) ""(96.52,-25.4) ""(96.52,-22.86) ""(96.52,-20.32) ""(96.52,-17.78) ""(96.52,-15.24) ""(96.52,-12.7) ""(96.52,-10.16) ""(96.52,-7.62) ""(96.52,-5.08) ""(96.52,-2.54) ""(99.06,-48.26) ""(99.06,-45.72) ""(99.06,-43.18) ""(99.06,-40.64) ""(99.06,-38.1) ""(99.06,-35.56) ""(99.06,-33.02) ""(99.06,-30.48) ""(99.06,-27.94) ""(99.06,-25.4) ""(99.06,-22.86) ""(99.06,-20.32) ""(99.06,-17.78) ""(99.06,-15.24) ""(99.06,-12.7) ""(99.06,-10.16) ""(99.06,-7.62) ""(99.06,-5.08) ""(99.06,-2.54)
Top Overlay:
  lines w0.2: -2.54,-48.26 -1.27,-48.26 ; -2.54,-35.56 -1.27,-35.56 ; -2.54,-22.86 -1.27,-22.86 ; -2.54,-10.16 -1.27,-10.16 ; 100.33,-48.26 101.6,-48.26 ; 100.33,-35.56 101.6,-35.56 ; 100.33,-22.86 101.6,-22.86 ; 100.33,-10.16 101.6,-10.16
  lines w0.254: -2.54,1.27 -1.27,2.54 ; 0,1.27 0,2.54 ; 10.16,1.27 10.16,2.54 ; 22.86,1.27 22.86,2.54 ; 35.56,1.27 35.56,2.54 ; 48.26,1.27 48.26,2.54 ; 60.96,1.27 60.96,2.54 ; 73.66,1.27 73.66,2.54 ; 86.36,1.27 86.36,2.54 ; 99.06,1.27 99.06,2.54 ; -2.54,-50.8 -2.54,2.54 101.6,2.54 101.6,-50.8 -2.54,-50.8

## PROTOTYPE_AREA - 55 [mm] "Prototype area; 40 cols x 20 rows"
pads (1100):
  round 1.8 hole 0.9: 1(0,0) 2(2.54,0) 3(5.08,0) 4(7.62,0) 5(10.16,0) 6(12.7,0) 7(15.24,0) 8(17.78,0) 9(20.32,0) 10(22.86,0) 11(25.4,0) 12(27.94,0) 13(30.48,0) 14(33.02,0) 15(35.56,0) 16(38.1,0) 17(40.64,0) 18(43.18,0) 19(45.72,0) 20(48.26,0) 21(50.8,0) 22(53.34,0) 23(55.88,0) 24(58.42,0) 25(60.96,0) 26(63.5,0) 27(66.04,0) 28(68.58,0) 29(71.12,0) 30(73.66,0) 31(76.2,0) 32(78.74,0) 33(81.28,0) 34(83.82,0) 35(86.36,0) 36(88.9,0) 37(91.44,0) 38(93.98,0) 39(96.52,0) 40(99.06,0) 41(101.6,0) 42(104.14,0) 43(106.68,0) 44(109.22,0) 45(111.76,0) 46(114.3,0) 47(116.84,0) 48(119.38,0) 49(121.92,0) 50(124.46,0) 51(127,0) 52(129.54,0) 53(132.08,0) 54(134.62,0) 55(137.16,0) ""(0,-48.26) ""(0,-45.72) ""(0,-43.18) ""(0,-40.64) ""(0,-38.1) ""(0,-35.56) ""(0,-33.02) ""(0,-30.48) ""(0,-27.94) ""(0,-25.4) ""(0,-22.86) ""(0,-20.32) ""(0,-17.78) ""(0,-15.24) ""(0,-12.7) ""(0,-10.16) ""(0,-7.62) ""(0,-5.08) ""(0,-2.54) ""(2.54,-48.26) ""(2.54,-45.72) ""(2.54,-43.18) ""(2.54,-40.64) ""(2.54,-38.1) ""(2.54,-35.56) ""(2.54,-33.02) ""(2.54,-30.48) ""(2.54,-27.94) ""(2.54,-25.4) ""(2.54,-22.86) ""(2.54,-20.32) ""(2.54,-17.78) ""(2.54,-15.24) ""(2.54,-12.7) ""(2.54,-10.16) ""(2.54,-7.62) ""(2.54,-5.08) ""(2.54,-2.54) ""(5.08,-48.26) ""(5.08,-45.72) ""(5.08,-43.18) ""(5.08,-40.64) ""(5.08,-38.1) ""(5.08,-35.56) ""(5.08,-33.02) ""(5.08,-30.48) ""(5.08,-27.94) ""(5.08,-25.4) ""(5.08,-22.86) ""(5.08,-20.32) ""(5.08,-17.78) ""(5.08,-15.24) ""(5.08,-12.7) ""(5.08,-10.16) ""(5.08,-7.62) ""(5.08,-5.08) ""(5.08,-2.54) ""(7.62,-48.26) ""(7.62,-45.72) ""(7.62,-43.18) ""(7.62,-40.64) ""(7.62,-38.1) ""(7.62,-35.56) ""(7.62,-33.02) ""(7.62,-30.48) ""(7.62,-27.94) ""(7.62,-25.4) ""(7.62,-22.86) ""(7.62,-20.32) ""(7.62,-17.78) ""(7.62,-15.24) ""(7.62,-12.7) ""(7.62,-10.16) ""(7.62,-7.62) ""(7.62,-5.08) ""(7.62,-2.54) ""(10.16,-48.26) ""(10.16,-45.72) ""(10.16,-43.18) ""(10.16,-40.64) ""(10.16,-38.1) ""(10.16,-35.56) ""(10.16,-33.02) ""(10.16,-30.48) ""(10.16,-27.94) ""(10.16,-25.4) ""(10.16,-22.86) ""(10.16,-20.32) ""(10.16,-17.78) ""(10.16,-15.24) ""(10.16,-12.7) ""(10.16,-10.16) ""(10.16,-7.62) ""(10.16,-5.08) ""(10.16,-2.54) ""(12.7,-48.26) ""(12.7,-45.72) ""(12.7,-43.18) ""(12.7,-40.64) ""(12.7,-38.1) ""(12.7,-35.56) ""(12.7,-33.02) ""(12.7,-30.48) ""(12.7,-27.94) ""(12.7,-25.4) ""(12.7,-22.86) ""(12.7,-20.32) ""(12.7,-17.78) ""(12.7,-15.24) ""(12.7,-12.7) ""(12.7,-10.16) ""(12.7,-7.62) ""(12.7,-5.08) ""(12.7,-2.54) ""(15.24,-48.26) ""(15.24,-45.72) ""(15.24,-43.18) ""(15.24,-40.64) ""(15.24,-38.1) ""(15.24,-35.56) ""(15.24,-33.02) ""(15.24,-30.48) ""(15.24,-27.94) ""(15.24,-25.4) ""(15.24,-22.86) ""(15.24,-20.32) ""(15.24,-17.78) ""(15.24,-15.24) ""(15.24,-12.7) ""(15.24,-10.16) ""(15.24,-7.62) ""(15.24,-5.08) ""(15.24,-2.54) ""(17.78,-48.26) ""(17.78,-45.72) ""(17.78,-43.18) ""(17.78,-40.64) ""(17.78,-38.1) ""(17.78,-35.56) ""(17.78,-33.02) ""(17.78,-30.48) ""(17.78,-27.94) ""(17.78,-25.4) ""(17.78,-22.86) ""(17.78,-20.32) ""(17.78,-17.78) ""(17.78,-15.24) ""(17.78,-12.7) ""(17.78,-10.16) ""(17.78,-7.62) ""(17.78,-5.08) ""(17.78,-2.54) ""(20.32,-48.26) ""(20.32,-45.72) ""(20.32,-43.18) ""(20.32,-40.64) ""(20.32,-38.1) ""(20.32,-35.56) ""(20.32,-33.02) ""(20.32,-30.48) ""(20.32,-27.94) ""(20.32,-25.4) ""(20.32,-22.86) ""(20.32,-20.32) ""(20.32,-17.78) ""(20.32,-15.24) ""(20.32,-12.7) ""(20.32,-10.16) ""(20.32,-7.62) ""(20.32,-5.08) ""(20.32,-2.54) ""(22.86,-48.26) ""(22.86,-45.72) ""(22.86,-43.18) ""(22.86,-40.64) ""(22.86,-38.1) ""(22.86,-35.56) ""(22.86,-33.02) ""(22.86,-30.48) ""(22.86,-27.94) ""(22.86,-25.4) ""(22.86,-22.86) ""(22.86,-20.32) ""(22.86,-17.78) ""(22.86,-15.24) ""(22.86,-12.7) ""(22.86,-10.16) ""(22.86,-7.62) ""(22.86,-5.08) ""(22.86,-2.54) ""(25.4,-48.26) ""(25.4,-45.72) ""(25.4,-43.18) ""(25.4,-40.64) ""(25.4,-38.1) ""(25.4,-35.56) ""(25.4,-33.02) ""(25.4,-30.48) ""(25.4,-27.94) ""(25.4,-25.4) ""(25.4,-22.86) ""(25.4,-20.32) ""(25.4,-17.78) ""(25.4,-15.24) ""(25.4,-12.7) ""(25.4,-10.16) ""(25.4,-7.62) ""(25.4,-5.08) ""(25.4,-2.54) ""(27.94,-48.26) ""(27.94,-45.72) ""(27.94,-43.18) ""(27.94,-40.64) ""(27.94,-38.1) ""(27.94,-35.56) ""(27.94,-33.02) ""(27.94,-30.48) ""(27.94,-27.94) ""(27.94,-25.4) ""(27.94,-22.86) ""(27.94,-20.32) ""(27.94,-17.78) ""(27.94,-15.24) ""(27.94,-12.7) ""(27.94,-10.16) ""(27.94,-7.62) ""(27.94,-5.08) ""(27.94,-2.54) ""(30.48,-48.26) ""(30.48,-45.72) ""(30.48,-43.18) ""(30.48,-40.64) ""(30.48,-38.1) ""(30.48,-35.56) ""(30.48,-33.02) ""(30.48,-30.48) ""(30.48,-27.94) ""(30.48,-25.4) ""(30.48,-22.86) ""(30.48,-20.32) ""(30.48,-17.78) ""(30.48,-15.24) ""(30.48,-12.7) ""(30.48,-10.16) ""(30.48,-7.62) ""(30.48,-5.08) ""(30.48,-2.54) ""(33.02,-48.26) ""(33.02,-45.72) ""(33.02,-43.18) ""(33.02,-40.64) ""(33.02,-38.1) ""(33.02,-35.56) ""(33.02,-33.02) ""(33.02,-30.48) ""(33.02,-27.94) ""(33.02,-25.4) ""(33.02,-22.86) ""(33.02,-20.32) ""(33.02,-17.78) ""(33.02,-15.24) ""(33.02,-12.7) ""(33.02,-10.16) ""(33.02,-7.62) ""(33.02,-5.08) ""(33.02,-2.54) ""(35.56,-48.26) ""(35.56,-45.72) ""(35.56,-43.18) ""(35.56,-40.64) ""(35.56,-38.1) ""(35.56,-35.56) ""(35.56,-33.02) ""(35.56,-30.48) ""(35.56,-27.94) ""(35.56,-25.4) ""(35.56,-22.86) ""(35.56,-20.32) ""(35.56,-17.78) ""(35.56,-15.24) ""(35.56,-12.7) ""(35.56,-10.16) ""(35.56,-7.62) ""(35.56,-5.08) ""(35.56,-2.54) ""(38.1,-48.26) ""(38.1,-45.72) ""(38.1,-43.18) ""(38.1,-40.64) ""(38.1,-38.1) ""(38.1,-35.56) ""(38.1,-33.02) ""(38.1,-30.48) ""(38.1,-27.94) ""(38.1,-25.4) ""(38.1,-22.86) ""(38.1,-20.32) ""(38.1,-17.78) ""(38.1,-15.24) ""(38.1,-12.7) ""(38.1,-10.16) ""(38.1,-7.62) ""(38.1,-5.08) ""(38.1,-2.54) ""(40.64,-48.26) ""(40.64,-45.72) ""(40.64,-43.18) ""(40.64,-40.64) ""(40.64,-38.1) ""(40.64,-35.56) ""(40.64,-33.02) ""(40.64,-30.48) ""(40.64,-27.94) ""(40.64,-25.4) ""(40.64,-22.86) ""(40.64,-20.32) ""(40.64,-17.78) ""(40.64,-15.24) ""(40.64,-12.7) ""(40.64,-10.16) ""(40.64,-7.62) ""(40.64,-5.08) ""(40.64,-2.54) ""(43.18,-48.26) ""(43.18,-45.72) ""(43.18,-43.18) ""(43.18,-40.64) ""(43.18,-38.1) ""(43.18,-35.56) ""(43.18,-33.02) ""(43.18,-30.48) ""(43.18,-27.94) ""(43.18,-25.4) ""(43.18,-22.86) ""(43.18,-20.32) ""(43.18,-17.78) ""(43.18,-15.24) ""(43.18,-12.7) ""(43.18,-10.16) ""(43.18,-7.62) ""(43.18,-5.08) ""(43.18,-2.54) ""(45.72,-48.26) ""(45.72,-45.72) ""(45.72,-43.18) ""(45.72,-40.64) ""(45.72,-38.1) ""(45.72,-35.56) ""(45.72,-33.02) ""(45.72,-30.48) ""(45.72,-27.94) ""(45.72,-25.4) ""(45.72,-22.86) ""(45.72,-20.32) ""(45.72,-17.78) ""(45.72,-15.24) ""(45.72,-12.7) ""(45.72,-10.16) ""(45.72,-7.62) ""(45.72,-5.08) ""(45.72,-2.54) ""(48.26,-48.26) ""(48.26,-45.72) ""(48.26,-43.18) ""(48.26,-40.64) ""(48.26,-38.1) ""(48.26,-35.56) ""(48.26,-33.02) ""(48.26,-30.48) ""(48.26,-27.94) ""(48.26,-25.4) ""(48.26,-22.86) ""(48.26,-20.32) ""(48.26,-17.78) ""(48.26,-15.24) ""(48.26,-12.7) ""(48.26,-10.16) ""(48.26,-7.62) ""(48.26,-5.08) ""(48.26,-2.54) ""(50.8,-48.26) ""(50.8,-45.72) ""(50.8,-43.18) ""(50.8,-40.64) ""(50.8,-38.1) ""(50.8,-35.56) ""(50.8,-33.02) ""(50.8,-30.48) ""(50.8,-27.94) ""(50.8,-25.4) ""(50.8,-22.86) ""(50.8,-20.32) ""(50.8,-17.78) ""(50.8,-15.24) ""(50.8,-12.7) ""(50.8,-10.16) ""(50.8,-7.62) ""(50.8,-5.08) ""(50.8,-2.54) ""(53.34,-48.26) ""(53.34,-45.72) ""(53.34,-43.18) ""(53.34,-40.64) ""(53.34,-38.1) ""(53.34,-35.56) ""(53.34,-33.02) ""(53.34,-30.48) ""(53.34,-27.94) ""(53.34,-25.4) ""(53.34,-22.86) ""(53.34,-20.32) ""(53.34,-17.78) ""(53.34,-15.24) ""(53.34,-12.7) ""(53.34,-10.16) ""(53.34,-7.62) ""(53.34,-5.08) ""(53.34,-2.54) ""(55.88,-48.26) ""(55.88,-45.72) ""(55.88,-43.18) ""(55.88,-40.64) ""(55.88,-38.1) ""(55.88,-35.56) ""(55.88,-33.02) ""(55.88,-30.48) ""(55.88,-27.94) ""(55.88,-25.4) ""(55.88,-22.86) ""(55.88,-20.32) ""(55.88,-17.78) ""(55.88,-15.24) ""(55.88,-12.7) ""(55.88,-10.16) ""(55.88,-7.62) ""(55.88,-5.08) ""(55.88,-2.54) ""(58.42,-48.26) ""(58.42,-45.72) ""(58.42,-43.18) ""(58.42,-40.64) ""(58.42,-38.1) ""(58.42,-35.56) ""(58.42,-33.02) ""(58.42,-30.48) ""(58.42,-27.94) ""(58.42,-25.4) ""(58.42,-22.86) ""(58.42,-20.32) ""(58.42,-17.78) ""(58.42,-15.24) ""(58.42,-12.7) ""(58.42,-10.16) ""(58.42,-7.62) ""(58.42,-5.08) ""(58.42,-2.54) ""(60.96,-48.26) ""(60.96,-45.72) ""(60.96,-43.18) ""(60.96,-40.64) ""(60.96,-38.1) ""(60.96,-35.56) ""(60.96,-33.02) ""(60.96,-30.48) ""(60.96,-27.94) ""(60.96,-25.4) ""(60.96,-22.86) ""(60.96,-20.32) ""(60.96,-17.78) ""(60.96,-15.24) ""(60.96,-12.7) ""(60.96,-10.16) ""(60.96,-7.62) ""(60.96,-5.08) ""(60.96,-2.54) ""(63.5,-48.26) ""(63.5,-45.72) ""(63.5,-43.18) ""(63.5,-40.64) ""(63.5,-38.1) ""(63.5,-35.56) ""(63.5,-33.02) ""(63.5,-30.48) ""(63.5,-27.94) ""(63.5,-25.4) ""(63.5,-22.86) ""(63.5,-20.32) ""(63.5,-17.78) ""(63.5,-15.24) ""(63.5,-12.7) ""(63.5,-10.16) ""(63.5,-7.62) ""(63.5,-5.08) ""(63.5,-2.54) ""(66.04,-48.26) ""(66.04,-45.72) ""(66.04,-43.18) ""(66.04,-40.64) ""(66.04,-38.1) ""(66.04,-35.56) ""(66.04,-33.02) ""(66.04,-30.48) ""(66.04,-27.94) ""(66.04,-25.4) ""(66.04,-22.86) ""(66.04,-20.32) ""(66.04,-17.78) ""(66.04,-15.24) ""(66.04,-12.7) ""(66.04,-10.16) ""(66.04,-7.62) ""(66.04,-5.08) ""(66.04,-2.54) ""(68.58,-48.26) ""(68.58,-45.72) ""(68.58,-43.18) ""(68.58,-40.64) ""(68.58,-38.1) ""(68.58,-35.56) ""(68.58,-33.02) ""(68.58,-30.48) ""(68.58,-27.94) ""(68.58,-25.4) ""(68.58,-22.86) ""(68.58,-20.32) ""(68.58,-17.78) ""(68.58,-15.24) ""(68.58,-12.7) ""(68.58,-10.16) ""(68.58,-7.62) ""(68.58,-5.08) ""(68.58,-2.54) ""(71.12,-48.26) ""(71.12,-45.72) ""(71.12,-43.18) ""(71.12,-40.64) ""(71.12,-38.1) ""(71.12,-35.56) ""(71.12,-33.02) ""(71.12,-30.48) ""(71.12,-27.94) ""(71.12,-25.4) ""(71.12,-22.86) ""(71.12,-20.32) ""(71.12,-17.78) ""(71.12,-15.24) ""(71.12,-12.7) ""(71.12,-10.16) ""(71.12,-7.62) ""(71.12,-5.08) ""(71.12,-2.54) ""(73.66,-48.26) ""(73.66,-45.72) ""(73.66,-43.18) ""(73.66,-40.64) ""(73.66,-38.1) ""(73.66,-35.56) ""(73.66,-33.02) ""(73.66,-30.48) ""(73.66,-27.94) ""(73.66,-25.4) ""(73.66,-22.86) ""(73.66,-20.32) ""(73.66,-17.78) ""(73.66,-15.24) ""(73.66,-12.7) ""(73.66,-10.16) ""(73.66,-7.62) ""(73.66,-5.08) ""(73.66,-2.54) ""(76.2,-48.26) ""(76.2,-45.72) ""(76.2,-43.18) ""(76.2,-40.64) ""(76.2,-38.1) ""(76.2,-35.56) ""(76.2,-33.02) ""(76.2,-30.48) ""(76.2,-27.94) ""(76.2,-25.4) ""(76.2,-22.86) ""(76.2,-20.32) ""(76.2,-17.78) ""(76.2,-15.24) ""(76.2,-12.7) ""(76.2,-10.16) ""(76.2,-7.62) ""(76.2,-5.08) ""(76.2,-2.54) ""(78.74,-48.26) ""(78.74,-45.72) ""(78.74,-43.18) ""(78.74,-40.64) ""(78.74,-38.1) ""(78.74,-35.56) ""(78.74,-33.02) ""(78.74,-30.48) ""(78.74,-27.94) ""(78.74,-25.4) ""(78.74,-22.86) ""(78.74,-20.32) ""(78.74,-17.78) ""(78.74,-15.24) ""(78.74,-12.7) ""(78.74,-10.16) ""(78.74,-7.62) ""(78.74,-5.08) ""(78.74,-2.54) ""(81.28,-48.26) ""(81.28,-45.72) ""(81.28,-43.18) ""(81.28,-40.64) ""(81.28,-38.1) ""(81.28,-35.56) ""(81.28,-33.02) ""(81.28,-30.48) ""(81.28,-27.94) ""(81.28,-25.4) ""(81.28,-22.86) ""(81.28,-20.32) ""(81.28,-17.78) ""(81.28,-15.24) ""(81.28,-12.7) ""(81.28,-10.16) ""(81.28,-7.62) ""(81.28,-5.08) ""(81.28,-2.54) ""(83.82,-48.26) ""(83.82,-45.72) ""(83.82,-43.18) ""(83.82,-40.64) ""(83.82,-38.1) ""(83.82,-35.56) ""(83.82,-33.02) ""(83.82,-30.48) ""(83.82,-27.94) ""(83.82,-25.4) ""(83.82,-22.86) ""(83.82,-20.32) ""(83.82,-17.78) ""(83.82,-15.24) ""(83.82,-12.7) ""(83.82,-10.16) ""(83.82,-7.62) ""(83.82,-5.08) ""(83.82,-2.54) ""(86.36,-48.26) ""(86.36,-45.72) ""(86.36,-43.18) ""(86.36,-40.64) ""(86.36,-38.1) ""(86.36,-35.56) ""(86.36,-33.02) ""(86.36,-30.48) ""(86.36,-27.94) ""(86.36,-25.4) ""(86.36,-22.86) ""(86.36,-20.32) ""(86.36,-17.78) ""(86.36,-15.24) ""(86.36,-12.7) ""(86.36,-10.16) ""(86.36,-7.62) ""(86.36,-5.08) ""(86.36,-2.54) ""(88.9,-48.26) ""(88.9,-45.72) ""(88.9,-43.18) ""(88.9,-40.64) ""(88.9,-38.1) ""(88.9,-35.56) ""(88.9,-33.02) ""(88.9,-30.48) ""(88.9,-27.94) ""(88.9,-25.4) ""(88.9,-22.86) ""(88.9,-20.32) ""(88.9,-17.78) ""(88.9,-15.24) ""(88.9,-12.7) ""(88.9,-10.16) ""(88.9,-7.62) ""(88.9,-5.08) ""(88.9,-2.54) ""(91.44,-48.26) ""(91.44,-45.72) ""(91.44,-43.18) ""(91.44,-40.64) ""(91.44,-38.1) ""(91.44,-35.56) ""(91.44,-33.02) ""(91.44,-30.48) ""(91.44,-27.94) ""(91.44,-25.4) ""(91.44,-22.86) ""(91.44,-20.32) ""(91.44,-17.78) ""(91.44,-15.24) ""(91.44,-12.7) ""(91.44,-10.16) ""(91.44,-7.62) ""(91.44,-5.08) ""(91.44,-2.54) ""(93.98,-48.26) ""(93.98,-45.72) ""(93.98,-43.18) ""(93.98,-40.64) ""(93.98,-38.1) ""(93.98,-35.56) ""(93.98,-33.02) ""(93.98,-30.48) ""(93.98,-27.94) ""(93.98,-25.4) ""(93.98,-22.86) ""(93.98,-20.32) ""(93.98,-17.78) ""(93.98,-15.24) ""(93.98,-12.7) ""(93.98,-10.16) ""(93.98,-7.62) ""(93.98,-5.08) ""(93.98,-2.54) ""(96.52,-48.26) ""(96.52,-45.72) ""(96.52,-43.18) ""(96.52,-40.64) ""(96.52,-38.1) ""(96.52,-35.56) ""(96.52,-33.02) ""(96.52,-30.48) ""(96.52,-27.94) ""(96.52,-25.4) ""(96.52,-22.86) ""(96.52,-20.32) ""(96.52,-17.78) ""(96.52,-15.24) ""(96.52,-12.7) ""(96.52,-10.16) ""(96.52,-7.62) ""(96.52,-5.08) ""(96.52,-2.54) ""(99.06,-48.26) ""(99.06,-45.72) ""(99.06,-43.18) ""(99.06,-40.64) ""(99.06,-38.1) ""(99.06,-35.56) ""(99.06,-33.02) ""(99.06,-30.48) ""(99.06,-27.94) ""(99.06,-25.4) ""(99.06,-22.86) ""(99.06,-20.32) ""(99.06,-17.78) ""(99.06,-15.24) ""(99.06,-12.7) ""(99.06,-10.16) ""(99.06,-7.62) ""(99.06,-5.08) ""(99.06,-2.54) ""(101.6,-48.26) ""(101.6,-45.72) ""(101.6,-43.18) ""(101.6,-40.64) ""(101.6,-38.1) ""(101.6,-35.56) ""(101.6,-33.02) ""(101.6,-30.48) ""(101.6,-27.94) ""(101.6,-25.4) ""(101.6,-22.86) ""(101.6,-20.32) ""(101.6,-17.78) ""(101.6,-15.24) ""(101.6,-12.7) ""(101.6,-10.16) ""(101.6,-7.62) ""(101.6,-5.08) ""(101.6,-2.54) ""(104.14,-48.26) ""(104.14,-45.72) ""(104.14,-43.18) ""(104.14,-40.64) ""(104.14,-38.1) ""(104.14,-35.56) ""(104.14,-33.02) ""(104.14,-30.48) ""(104.14,-27.94) ""(104.14,-25.4) ""(104.14,-22.86) ""(104.14,-20.32) ""(104.14,-17.78) ""(104.14,-15.24) ""(104.14,-12.7) ""(104.14,-10.16) ""(104.14,-7.62) ""(104.14,-5.08) ""(104.14,-2.54) ""(106.68,-48.26) ""(106.68,-45.72) ""(106.68,-43.18) ""(106.68,-40.64) ""(106.68,-38.1) ""(106.68,-35.56) ""(106.68,-33.02) ""(106.68,-30.48) ""(106.68,-27.94) ""(106.68,-25.4) ""(106.68,-22.86) ""(106.68,-20.32) ""(106.68,-17.78) ""(106.68,-15.24) ""(106.68,-12.7) ""(106.68,-10.16) ""(106.68,-7.62) ""(106.68,-5.08) ""(106.68,-2.54) ""(109.22,-48.26) ""(109.22,-45.72) ""(109.22,-43.18) ""(109.22,-40.64) ""(109.22,-38.1) ""(109.22,-35.56) ""(109.22,-33.02) ""(109.22,-30.48) ""(109.22,-27.94) ""(109.22,-25.4) ""(109.22,-22.86) ""(109.22,-20.32) ""(109.22,-17.78) ""(109.22,-15.24) ""(109.22,-12.7) ""(109.22,-10.16) ""(109.22,-7.62) ""(109.22,-5.08) ""(109.22,-2.54) ""(111.76,-48.26) ""(111.76,-45.72) ""(111.76,-43.18) ""(111.76,-40.64) ""(111.76,-38.1) ""(111.76,-35.56) ""(111.76,-33.02) ""(111.76,-30.48) ""(111.76,-27.94) ""(111.76,-25.4) ""(111.76,-22.86) ""(111.76,-20.32) ""(111.76,-17.78) ""(111.76,-15.24) ""(111.76,-12.7) ""(111.76,-10.16) ""(111.76,-7.62) ""(111.76,-5.08) ""(111.76,-2.54) ""(114.3,-48.26) ""(114.3,-45.72) ""(114.3,-43.18) ""(114.3,-40.64) ""(114.3,-38.1) ""(114.3,-35.56) ""(114.3,-33.02) ""(114.3,-30.48) ""(114.3,-27.94) ""(114.3,-25.4) ""(114.3,-22.86) ""(114.3,-20.32) ""(114.3,-17.78) ""(114.3,-15.24) ""(114.3,-12.7) ""(114.3,-10.16) ""(114.3,-7.62) ""(114.3,-5.08) ""(114.3,-2.54) ""(116.84,-48.26) ""(116.84,-45.72) ""(116.84,-43.18) ""(116.84,-40.64) ""(116.84,-38.1) ""(116.84,-35.56) ""(116.84,-33.02) ""(116.84,-30.48) ""(116.84,-27.94) ""(116.84,-25.4) ""(116.84,-22.86) ""(116.84,-20.32) ""(116.84,-17.78) ""(116.84,-15.24) ""(116.84,-12.7) ""(116.84,-10.16) ""(116.84,-7.62) ""(116.84,-5.08) ""(116.84,-2.54) ""(119.38,-48.26) ""(119.38,-45.72) ""(119.38,-43.18) ""(119.38,-40.64) ""(119.38,-38.1) ""(119.38,-35.56) ""(119.38,-33.02) ""(119.38,-30.48) ""(119.38,-27.94) ""(119.38,-25.4) ""(119.38,-22.86) ""(119.38,-20.32) ""(119.38,-17.78) ""(119.38,-15.24) ""(119.38,-12.7) ""(119.38,-10.16) ""(119.38,-7.62) ""(119.38,-5.08) ""(119.38,-2.54) ""(121.92,-48.26) ""(121.92,-45.72) ""(121.92,-43.18) ""(121.92,-40.64) ""(121.92,-38.1) ""(121.92,-35.56) ""(121.92,-33.02) ""(121.92,-30.48) ""(121.92,-27.94) ""(121.92,-25.4) ""(121.92,-22.86) ""(121.92,-20.32) ""(121.92,-17.78) ""(121.92,-15.24) ""(121.92,-12.7) ""(121.92,-10.16) ""(121.92,-7.62) ""(121.92,-5.08) ""(121.92,-2.54) ""(124.46,-48.26) ""(124.46,-45.72) ""(124.46,-43.18) ""(124.46,-40.64) ""(124.46,-38.1) ""(124.46,-35.56) ""(124.46,-33.02) ""(124.46,-30.48) ""(124.46,-27.94) ""(124.46,-25.4) ""(124.46,-22.86) ""(124.46,-20.32) ""(124.46,-17.78) ""(124.46,-15.24) ""(124.46,-12.7) ""(124.46,-10.16) ""(124.46,-7.62) ""(124.46,-5.08) ""(124.46,-2.54) ""(127,-48.26) ""(127,-45.72) ""(127,-43.18) ""(127,-40.64) ""(127,-38.1) ""(127,-35.56) ""(127,-33.02) ""(127,-30.48) ""(127,-27.94) ""(127,-25.4) ""(127,-22.86) ""(127,-20.32) ""(127,-17.78) ""(127,-15.24) ""(127,-12.7) ""(127,-10.16) ""(127,-7.62) ""(127,-5.08) ""(127,-2.54) ""(129.54,-48.26) ""(129.54,-45.72) ""(129.54,-43.18) ""(129.54,-40.64) ""(129.54,-38.1) ""(129.54,-35.56) ""(129.54,-33.02) ""(129.54,-30.48) ""(129.54,-27.94) ""(129.54,-25.4) ""(129.54,-22.86) ""(129.54,-20.32) ""(129.54,-17.78) ""(129.54,-15.24) ""(129.54,-12.7) ""(129.54,-10.16) ""(129.54,-7.62) ""(129.54,-5.08) ""(129.54,-2.54) ""(132.08,-48.26) ""(132.08,-45.72) ""(132.08,-43.18) ""(132.08,-40.64) ""(132.08,-38.1) ""(132.08,-35.56) ""(132.08,-33.02) ""(132.08,-30.48) ""(132.08,-27.94) ""(132.08,-25.4) ""(132.08,-22.86) ""(132.08,-20.32) ""(132.08,-17.78) ""(132.08,-15.24) ""(132.08,-12.7) ""(132.08,-10.16) ""(132.08,-7.62) ""(132.08,-5.08) ""(132.08,-2.54) ""(134.62,-48.26) ""(134.62,-45.72) ""(134.62,-43.18) ""(134.62,-40.64) ""(134.62,-38.1) ""(134.62,-35.56) ""(134.62,-33.02) ""(134.62,-30.48) ""(134.62,-27.94) ""(134.62,-25.4) ""(134.62,-22.86) ""(134.62,-20.32) ""(134.62,-17.78) ""(134.62,-15.24) ""(134.62,-12.7) ""(134.62,-10.16) ""(134.62,-7.62) ""(134.62,-5.08) ""(134.62,-2.54) ""(137.16,-48.26) ""(137.16,-45.72) ""(137.16,-43.18) ""(137.16,-40.64) ""(137.16,-38.1) ""(137.16,-35.56) ""(137.16,-33.02) ""(137.16,-30.48) ""(137.16,-27.94) ""(137.16,-25.4) ""(137.16,-22.86) ""(137.16,-20.32) ""(137.16,-17.78) ""(137.16,-15.24) ""(137.16,-12.7) ""(137.16,-10.16) ""(137.16,-7.62) ""(137.16,-5.08) ""(137.16,-2.54)
Top Layer:
  pour cut-out: -1.275,1.275 138.435,1.275 138.435,-49.535 -1.275,-49.535
Bottom Layer:
  pour cut-out: -1.275,1.275 138.435,1.275 138.435,-49.535 -1.275,-49.535
Top Overlay:
  lines w0.254: -1.275,-49.535 -1.275,1.275 138.435,1.275 138.435,-49.535 -1.275,-49.535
